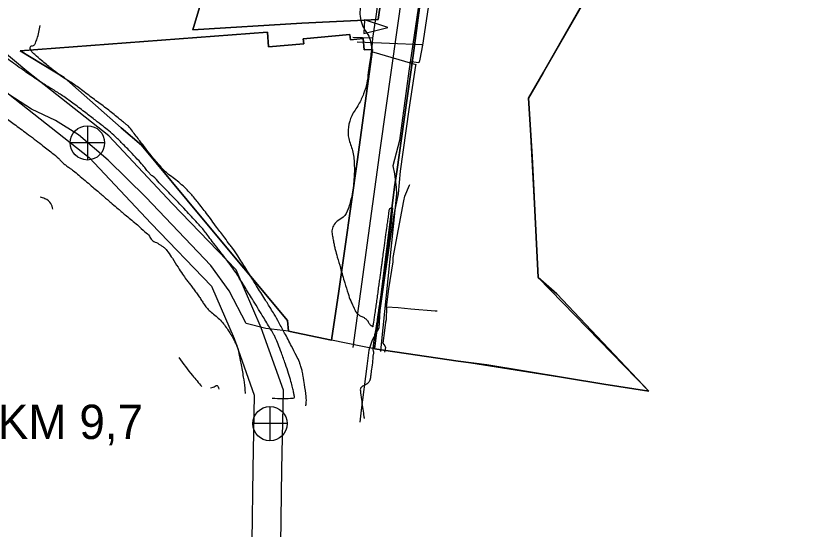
# Model space of a CAD drawing. Extents: x -478232 to -472707, y -1118753 to -1113967.
# Drawn here: x -476056.2 to -475825.3, y -1117737.7 to -1117588.2 of the extents above; entities that cross this region are included whole.
import ezdxf

# ---------------------------------------------------------------- set-up
doc = ezdxf.new("R2010")
doc.units = 0
for name, color, linetype in [('cesty', 7, 'Continuous'), ('nesmenovane pozemky', 7, 'Continuous'), ('ObPÚ', 7, 'Continuous'), ('plyn_stl', 7, 'Continuous'), ('silnice', 7, 'Continuous'), ('staničení toku', 7, 'Continuous'), ('telekomunikační kabel_O2', 7, 'Continuous'), ('VAK_vodovod', 7, 'Continuous'), ('VAK_vodovod_přípojky', 7, 'Continuous'), ('vodní plochy', 7, 'Continuous'), ('Vrstevnice_hlavni', 7, 'Continuous'), ('Vrstevnice_vedlejsi', 7, 'Continuous')]:
    doc.layers.add(name, color=color, linetype=linetype)

msp = doc.modelspace()

# ---------------------------------------------------------------- linework, layer by layer
at = {"layer": 'cesty'}
msp.add_line((-475954.611, -1117589.335), (-475954.743, -1117593.333), dxfattribs=at)
msp.add_lwpolyline([(-475954.743, -1117593.333), (-475947.734, -1117591.563), (-475954.611, -1117589.335)], dxfattribs=at)
at = {"layer": 'nesmenovane pozemky'}
for p, q in [((-475982.83, -1117592.88), (-476054.95, -1117598.38)), ((-475958.8, -1117593.62), (-475972.41, -1117594.83)), ((-475958.67, -1117595.15), (-475958.8, -1117593.62)), ((-475972.41, -1117594.83), (-475972.26, -1117596.35)), ((-475956.76, -1117594.96), (-475958.67, -1117595.15)), ((-475954.99, -1117594.75), (-475956.76, -1117594.96)), ((-476054.95, -1117598.38), (-476042.1, -1117606.13)), ((-476042.1, -1117606.13), (-476028.77, -1117617.9)), ((-476028.77, -1117617.9), (-476025.49, -1117620.79)), ((-476025.49, -1117620.79), (-476019.54, -1117625.79)), ((-476019.54, -1117625.79), (-476001.99, -1117647.03)), ((-475962.01, -1117668.38), (-475956.69, -1117630.64)), ((-476001.99, -1117647.03), (-475977.06, -1117676.86))]:
    msp.add_line(p, q, dxfattribs=at)
for points in [[(-475951.7, -1117685.1), (-475927.26, -1117688.72), (-475918.95, -1117689.8), (-475884.78, -1117695.44), (-475871.68, -1117697.52), (-475898.5, -1117669.12), (-475903.93, -1117664.35), (-475905.71, -1117629.13), (-475906.78, -1117612.16), (-475902.49, -1117604.75), (-475882.63, -1117570.25), (-475876.2, -1117558.77), (-475871.25, -1117549.71), (-475870.12, -1117548.49), (-475868.56, -1117541.56), (-475866.64, -1117537.01), (-475865.5, -1117532.56), (-475858.35, -1117525.46), (-475844.8, -1117506.28), (-475833.86, -1117486.94), (-475831.88, -1117483.59), (-475829.4, -1117473.48), (-475914.94, -1117458.35), (-475916.88, -1117458.16)], [(-475937.08, -1117500.29), (-475943.5, -1117540.53), (-475950.59, -1117589.22), (-475972.84, -1117590.29), (-476004.64, -1117592.26), (-475999.55, -1117575.26), (-475994.23, -1117573.44), (-475992.2, -1117563.25), (-475986.19, -1117534.11), (-475984.93, -1117525.82), (-475982.04, -1117518.19), (-475972.81, -1117513.2), (-475947.17, -1117503.84), (-475937.08, -1117500.29)], [(-475947.17, -1117503.84), (-475972.81, -1117513.2), (-475982.04, -1117518.19), (-475984.93, -1117525.82), (-475986.19, -1117534.11), (-475992.2, -1117563.25), (-475994.23, -1117573.44), (-475999.55, -1117575.26), (-476004.64, -1117592.26), (-475972.84, -1117590.29), (-475950.59, -1117589.22), (-475943.5, -1117540.53), (-475937.08, -1117500.29), (-475947.17, -1117503.84)], [(-475936.13, -1117566.09), (-475938.19, -1117582.83), (-475940.34, -1117599.73)], [(-475882.63, -1117570.25), (-475902.49, -1117604.75), (-475906.78, -1117612.16), (-475905.71, -1117629.13), (-475903.93, -1117664.35), (-475898.5, -1117669.12), (-475871.68, -1117697.52), (-475884.78, -1117695.44), (-475918.95, -1117689.8), (-475927.26, -1117688.72), (-475951.7, -1117685.1), (-475945.87, -1117637.95), (-475945.03, -1117632.93), (-475943.79, -1117623.91), (-475940.34, -1117599.73), (-475938.19, -1117582.83)], [(-476054.95, -1117598.38), (-475982.83, -1117592.88), (-475982.54, -1117597.23), (-475972.26, -1117596.35), (-475972.41, -1117594.83), (-475958.8, -1117593.62), (-475958.67, -1117595.15), (-475956.76, -1117594.96), (-475954.99, -1117594.75), (-475954.64, -1117598.05), (-475952.28, -1117597.96), (-475956.69, -1117630.64), (-475962.01, -1117668.38), (-475964.23, -1117682.64), (-475976.69, -1117679.99), (-475977.06, -1117676.86), (-476001.99, -1117647.03), (-476019.54, -1117625.79), (-476025.49, -1117620.79), (-476028.77, -1117617.9), (-476042.1, -1117606.13), (-476054.95, -1117598.38)], [(-475972.26, -1117596.35), (-475982.54, -1117597.23), (-475982.83, -1117592.88)], [(-475956.69, -1117630.64), (-475952.28, -1117597.96), (-475954.64, -1117598.05), (-475954.99, -1117594.75)], [(-475940.34, -1117599.73), (-475943.79, -1117623.91), (-475945.03, -1117632.93), (-475945.87, -1117637.95), (-475951.7, -1117685.1)], [(-475977.06, -1117676.86), (-475976.69, -1117679.99), (-475964.23, -1117682.64), (-475962.01, -1117668.38)]]:
    msp.add_lwpolyline(points, dxfattribs=at)
at = {"layer": 'ObPÚ'}
for points in [[(-475797.1, -1117434.24), (-475812.51, -1117451.24), (-475815.72, -1117464.29), (-475829.4, -1117473.48), (-475831.88, -1117483.59), (-475844.8, -1117506.28), (-475858.35, -1117525.46), (-475865.5, -1117532.56), (-475866.64, -1117537.01), (-475868.56, -1117541.56), (-475870.12, -1117548.49), (-475871.25, -1117549.71), (-475906.78, -1117612.16), (-475903.93, -1117664.35), (-475871.68, -1117697.52), (-475884.78, -1117695.44), (-475927.26, -1117688.72), (-475927.26, -1117688.72), (-475951.7, -1117685.1), (-475955.15, -1117684.42), (-475964.23, -1117682.64), (-475976.69, -1117679.99)], [(-475976.69, -1117679.99), (-475983.33, -1117679.27), (-475989.02, -1117677.74), (-475994.01, -1117668.3), (-475999.39, -1117660.91), (-476018.27, -1117641.02), (-476029.29, -1117630.21), (-476037.95, -1117622.81), (-476044.67, -1117618.64), (-476051.59, -1117615.33), (-476061.64, -1117608.91), (-476079.88, -1117594.07), (-476091, -1117580.9), (-476108.8, -1117553.82), (-476114, -1117528.42), (-476124.29, -1117530.11), (-476161.03, -1117531.19), (-476195.86, -1117533.14), (-476234.26, -1117534.63), (-476239.28, -1117534.9), (-476242.12, -1117534.97), (-476268.08, -1117536.08), (-476315.84, -1117537.76), (-476383.34, -1117541.03)]]:
    msp.add_lwpolyline(points, dxfattribs=at)
at = {"layer": 'plyn_stl'}
msp.add_line((-475952.244, -1117594.708), (-475958, -1117594.481), dxfattribs=at)
msp.add_lwpolyline([(-475950.891, -1117585.581), (-475951.277, -1117588.32), (-475951.277, -1117588.32), (-475952.244, -1117594.708), (-475952.569, -1117598.534), (-475951.885, -1117598.735), (-475939.635, -1117602.325), (-475939.681, -1117602.62), (-475941.682, -1117615.413), (-475944.166, -1117633.413), (-475944.166, -1117633.413), (-475944.769, -1117640.016), (-475945.933, -1117645.497), (-475946.953, -1117652.292), (-475950.061, -1117674.019), (-475950.384, -1117679.114), (-475952.306, -1117682.652), (-475953.329, -1117685.537), (-475953.931, -1117690.234), (-475955.586, -1117703.027), (-475955.894, -1117706.481)], dxfattribs=at)
at = {"layer": 'silnice'}
msp.add_lwpolyline([(-475957.898, -1117684.778), (-475949.882, -1117626.621), (-475938.626, -1117546.976), (-475927.029, -1117479.269), (-475917.649, -1117429.299), (-475903.982, -1117378.322)], dxfattribs=at)
at = {"layer": 'staničení toku'}
for p, q in [((-476035.323, -1117620.153), (-476035.323, -1117630.153)), ((-476030.323, -1117625.153), (-476040.323, -1117625.153)), ((-475982.122, -1117701.934), (-475982.122, -1117711.934)), ((-475977.122, -1117706.934), (-475987.122, -1117706.934))]:
    msp.add_line(p, q, dxfattribs=at)
for centre in [(-476035.323, -1117625.153), (-475982.122, -1117706.934)]:
    msp.add_circle(centre, 5, dxfattribs=at)
at = {"layer": 'telekomunikační kabel_O2'}
for points in [[(-475931.82, -1117535.04), (-475932.74, -1117541.33), (-475934.27, -1117556.02), (-475935.89, -1117566.02), (-475937.71, -1117577.81), (-475938.91, -1117585.91), (-475941.61, -1117604.26), (-475944.33, -1117624.51)], [(-475944.33, -1117624.51), (-475946.3, -1117631.82), (-475945.82, -1117634.15), (-475945.36, -1117638.18), (-475945.21, -1117640.05), (-475949.75, -1117683.81), (-475949.948, -1117685.946)], [(-475948.15, -1117672.99), (-475947.43, -1117667.7), (-475946.22, -1117659.8), (-475946.19, -1117658.58), (-475944.69, -1117650.28), (-475943.14, -1117642.06), (-475942.8, -1117640.69), (-475941.43, -1117637.45), (-475941.34, -1117637.26)], [(-475948.15, -1117672.99), (-475948.29, -1117676.74), (-475948.48, -1117677.36), (-475948.75, -1117679.85), (-475949.19, -1117683.52), (-475948.61, -1117684.28), (-475948.44, -1117684.72), (-475948.762, -1117686.113)], [(-475933.35, -1117674.2), (-475933.99, -1117674.13), (-475941.04, -1117673.59), (-475944.77, -1117673.16), (-475948.15, -1117672.99)]]:
    msp.add_lwpolyline(points, dxfattribs=at)
at = {"layer": 'VAK_vodovod'}
msp.add_lwpolyline([(-475961.022, -1117076.006), (-475947.88, -1117107.78), (-475947.26, -1117108.989), (-475886.863, -1117255.251), (-475879.338, -1117287.714), (-475878.218, -1117296.341), (-475877.862, -1117316.562), (-475878.829, -1117320.819), (-475879.236, -1117324.31), (-475879.403, -1117324.54), (-475921.268, -1117487.378), (-475934.347, -1117574.649), (-475937.667, -1117596.666), (-475938.465, -1117600.746), (-475938.582, -1117601.233), (-475938.757, -1117601.897), (-475940.979, -1117601.583)], dxfattribs=at)
at = {"layer": 'VAK_vodovod_přípojky'}
msp.add_lwpolyline([(-475937.667, -1117596.666), (-475937.9, -1117596.654), (-475956.701, -1117595.856)], dxfattribs=at)
at = {"layer": 'vodní plochy'}
for points in [[(-476156.309, -1117361.66), (-476163.99, -1117375.673), (-476163.99, -1117389.902), (-476152.92, -1117410.923), (-476142.297, -1117430.597), (-476130.77, -1117459.77), (-476124.441, -1117494.592), (-476117.774, -1117517.884), (-476114.889, -1117528.175), (-476108.171, -1117553.375), (-476083.318, -1117589.997), (-476058.349, -1117610.854), (-476034.844, -1117629.396), (-476016.763, -1117648.618), (-475999.131, -1117666.937), (-475992.574, -1117682.093), (-475986.696, -1117698.606), (-475987.148, -1117720.093), (-475987.374, -1117741.294), (-475990.765, -1117763.06), (-476002.517, -1117812.638), (-476018.337, -1117866.341), (-476031.898, -1117910.436), (-476051.109, -1117946.052)], [(-476043.664, -1117950.068), (-476024.057, -1117913.719), (-476010.237, -1117868.779), (-475994.339, -1117814.81), (-475982.458, -1117764.689), (-475978.922, -1117741.994), (-475978.69, -1117720.226), (-475978.206, -1117697.232), (-475984.699, -1117678.992), (-475991.975, -1117662.174), (-476010.635, -1117642.787), (-476029.112, -1117623.144), (-476053.017, -1117604.286), (-476076.984, -1117584.266), (-476100.367, -1117549.811), (-476106.73, -1117525.944), (-476109.636, -1117515.578), (-476116.194, -1117492.667), (-476122.596, -1117457.437), (-476134.615, -1117427.02), (-476145.456, -1117406.943), (-476155.531, -1117387.811), (-476155.531, -1117377.84), (-476148.691, -1117365.336)]]:
    msp.add_lwpolyline(points, dxfattribs=at)
at = {"layer": 'Vrstevnice_hlavni'}
for points in [[(-475971.717, -1117701.762), (-475971.607, -1117701.252), (-475971.588, -1117698.984), (-475972.084, -1117695.558), (-475972.453, -1117693.121), (-475972.695, -1117691.672), (-475972.81, -1117691.21), (-475972.989, -1117690.616), (-475973.23, -1117689.89), (-475973.535, -1117689.032), (-475974.407, -1117687.189), (-475975.847, -1117684.359), (-475977.854, -1117680.544), (-475979.53, -1117677.451), (-475980.877, -1117675.08), (-475981.894, -1117673.431), (-475983.613, -1117670.663), (-475986.035, -1117666.775), (-475989.159, -1117661.767), (-475991.493, -1117658.108), (-475993.035, -1117655.798), (-475993.787, -1117654.837), (-475995.305, -1117652.833), (-475997.589, -1117649.787), (-476000.639, -1117645.698), (-476003.172, -1117642.447), (-476005.187, -1117640.031), (-476006.686, -1117638.453), (-476008.271, -1117636.98), (-476009.945, -1117635.611), (-476011.706, -1117634.347), (-476013.975, -1117632.09), (-476016.751, -1117628.84), (-476020.034, -1117624.596), (-476022.231, -1117621.758), (-476023.343, -1117620.326), (-476023.368, -1117620.3), (-476023.492, -1117620.197), (-476023.714, -1117620.018), (-476024.035, -1117619.763), (-476024.775, -1117619.164), (-476025.934, -1117618.221), (-476027.511, -1117616.935), (-476029.117, -1117615.669), (-476030.752, -1117614.422), (-476032.416, -1117613.195), (-476034.102, -1117611.941), (-476035.809, -1117610.661), (-476037.537, -1117609.353), (-476039.113, -1117608.231), (-476040.537, -1117607.296), (-476041.807, -1117606.547), (-476043.59, -1117605.281), (-476045.886, -1117603.499), (-476048.694, -1117601.201), (-476050.647, -1117599.461), (-476051.746, -1117598.281), (-476051.991, -1117597.66), (-476051.957, -1117597.21), (-476051.643, -1117596.932), (-476051.051, -1117596.824), (-476050.503, -1117596.11), (-476050.001, -1117594.788), (-476049.087, -1117590.932)], [(-476045.367, -1117644.51), (-476045.958, -1117642.834), (-476047.71, -1117641.434), (-476049.108, -1117640.973)], [(-476008.671, -1117687.695), (-476004.74, -1117692.892), (-476001.978, -1117696.103)], [(-475999.442, -1117696.51), (-475998.676, -1117696.339), (-475997.525, -1117695.856), (-475997.026, -1117696.899)]]:
    msp.add_spline(points, degree=3, dxfattribs=at)
at = {"layer": 'Vrstevnice_vedlejsi'}
for points in [[(-475925.807, -1117448.34), (-475926.271, -1117450.621), (-475926.743, -1117453.028), (-475927.223, -1117455.562), (-475927.71, -1117458.222), (-475928.119, -1117460.397), (-475928.448, -1117462.085), (-475928.698, -1117463.287), (-475929.008, -1117464.755), (-475929.377, -1117466.489), (-475929.805, -1117468.489), (-475930.153, -1117470.183), (-475930.42, -1117471.572), (-475930.607, -1117472.656), (-475930.864, -1117474.203), (-475931.192, -1117476.212), (-475931.591, -1117478.685), (-475931.911, -1117480.673), (-475932.154, -1117482.178), (-475932.319, -1117483.199), (-475932.507, -1117484.336), (-475932.716, -1117485.589), (-475932.947, -1117486.958), (-475933.165, -1117488.181), (-475933.369, -1117489.257), (-475933.56, -1117490.186), (-475933.776, -1117491.179), (-475934.018, -1117492.236), (-475934.284, -1117493.357), (-475934.519, -1117494.236), (-475934.723, -1117494.873), (-475934.895, -1117495.268), (-475935.041, -1117495.607), (-475935.161, -1117495.889), (-475935.254, -1117496.115), (-475935.322, -1117496.274), (-475935.366, -1117496.367), (-475935.386, -1117496.394), (-475935.348, -1117496.507), (-475935.253, -1117496.706), (-475935.101, -1117496.991), (-475935.105, -1117497.404), (-475935.264, -1117497.944), (-475935.579, -1117498.612), (-475935.962, -1117499.972), (-475936.413, -1117502.024), (-475936.932, -1117504.768), (-475937.635, -1117508.885), (-475938.521, -1117514.375), (-475939.592, -1117521.239), (-475940.344, -1117525.997), (-475940.776, -1117528.651), (-475940.89, -1117529.2), (-475940.962, -1117529.609), (-475940.994, -1117529.877), (-475940.984, -1117530.005), (-475940.975, -1117530.143), (-475940.967, -1117530.29), (-475940.96, -1117530.446), (-475940.993, -1117530.576), (-475941.066, -1117530.679), (-475941.18, -1117530.754), (-475941.378, -1117530.99), (-475941.658, -1117531.386), (-475942.021, -1117531.943), (-475942.311, -1117532.508), (-475942.528, -1117533.081), (-475942.672, -1117533.663), (-475942.827, -1117534.113), (-475942.993, -1117534.43), (-475943.171, -1117534.615), (-475943.259, -1117535.054), (-475943.258, -1117535.746), (-475943.166, -1117536.692), (-475943.05, -1117537.531), (-475942.909, -1117538.261), (-475942.742, -1117538.884), (-475942.673, -1117539.509), (-475942.701, -1117540.138), (-475942.826, -1117540.769), (-475943.252, -1117541.788), (-475943.979, -1117543.194), (-475945.007, -1117544.986), (-475946.021, -1117548.378), (-475947.023, -1117553.369), (-475948.011, -1117559.959), (-475949.315, -1117565.973), (-475950.935, -1117571.413), (-475952.871, -1117576.278), (-475954.339, -1117580.395), (-475955.339, -1117583.764), (-475955.87, -1117586.385), (-475955.761, -1117588.893), (-475955.011, -1117591.286), (-475953.62, -1117593.565), (-475952.783, -1117595.731), (-475952.5, -1117597.782)], [(-475981.46, -1117699.481), (-475978.555, -1117699.624), (-475976.129, -1117699.562), (-475974.954, -1117699.271), (-475975.03, -1117698.751), (-475975.228, -1117697.811), (-475975.55, -1117696.45), (-475975.994, -1117694.67), (-475976.683, -1117692.38), (-475977.615, -1117689.58), (-475978.79, -1117686.27), (-475979.742, -1117683.744), (-475980.471, -1117682), (-475980.976, -1117681.039), (-475982.274, -1117678.84), (-475984.365, -1117675.402), (-475987.248, -1117670.725), (-475989.482, -1117667.108), (-475991.066, -1117664.551), (-475992, -1117663.054), (-475993.334, -1117661.147), (-475995.067, -1117658.83), (-475997.2, -1117656.104), (-475998.937, -1117653.864), (-476000.278, -1117652.111), (-476001.223, -1117650.844), (-476003.359, -1117648.412), (-476006.686, -1117644.817), (-476011.205, -1117640.057), (-476014.372, -1117636.772), (-476016.189, -1117634.963), (-476016.654, -1117634.629), (-476017.253, -1117634.033), (-476017.986, -1117633.174), (-476018.854, -1117632.053), (-476020.293, -1117630.419), (-476022.304, -1117628.273), (-476024.886, -1117625.614), (-476027.159, -1117623.402), (-476029.122, -1117621.638), (-476030.775, -1117620.322), (-476033.001, -1117618.591), (-476035.8, -1117616.445), (-476039.172, -1117613.884), (-476042.252, -1117611.681), (-476045.041, -1117609.835), (-476047.539, -1117608.347), (-476050.577, -1117606.371), (-476054.156, -1117603.908), (-476058.275, -1117600.957), (-476062.207, -1117598.083), (-476065.949, -1117595.284), (-476069.503, -1117592.56), (-476072.061, -1117590.57), (-476073.624, -1117589.313), (-476074.192, -1117588.788), (-476074.683, -1117588.4), (-476075.099, -1117588.149), (-476075.44, -1117588.034), (-476076.24, -1117587.297), (-476077.502, -1117585.938), (-476079.224, -1117583.956), (-476080.447, -1117582.527), (-476081.171, -1117581.65), (-476081.395, -1117581.326), (-476081.696, -1117580.862), (-476082.073, -1117580.259), (-476082.526, -1117579.516), (-476083.525, -1117577.807), (-476085.071, -1117575.131), (-476087.164, -1117571.488), (-476088.854, -1117568.526), (-476090.141, -1117566.244), (-476091.025, -1117564.644), (-476092.063, -1117562.712), (-476093.256, -1117560.449), (-476094.602, -1117557.855), (-476095.618, -1117555.794), (-476096.304, -1117554.266), (-476096.659, -1117553.272), (-476097.351, -1117551.32), (-476098.38, -1117548.411), (-476099.746, -1117544.544), (-476100.765, -1117541.586), (-476101.438, -1117539.537), (-476101.763, -1117538.395), (-476102.235, -1117536.609), (-476102.852, -1117534.179), (-476103.615, -1117531.104), (-476104.476, -1117527.462), (-476105.437, -1117523.255)], [(-476106.817, -1117565.137), (-476105.765, -1117567.124), (-476104.847, -1117568.952), (-476104.064, -1117570.621), (-476103.415, -1117572.131), (-476102.764, -1117573.351), (-476102.11, -1117574.281), (-476101.453, -1117574.921), (-476100.89, -1117575.71), (-476100.42, -1117576.65), (-476100.044, -1117577.739), (-476099.46, -1117578.945), (-476098.67, -1117580.267), (-476097.672, -1117581.706), (-476096.764, -1117583.004), (-476095.947, -1117584.161), (-476095.22, -1117585.179), (-476094.396, -1117586.266), (-476093.475, -1117587.421), (-476092.456, -1117588.646), (-476091.223, -1117590.178), (-476089.774, -1117592.02), (-476088.11, -1117594.169), (-476086.729, -1117595.938), (-476085.632, -1117597.326), (-476084.818, -1117598.334), (-476083.928, -1117599.313), (-476082.959, -1117600.263), (-476081.914, -1117601.183), (-476080.423, -1117602.407), (-476078.488, -1117603.934), (-476076.108, -1117605.764), (-476073.547, -1117607.692), (-476070.805, -1117609.717), (-476067.883, -1117611.841), (-476065.083, -1117613.835), (-476062.404, -1117615.699), (-476059.847, -1117617.433), (-476056.711, -1117619.675), (-476052.997, -1117622.425), (-476048.704, -1117625.682), (-476045.603, -1117628.112), (-476043.694, -1117629.717), (-476042.976, -1117630.495), (-476042.176, -1117631.234), (-476041.295, -1117631.933), (-476040.332, -1117632.593), (-476039.042, -1117633.586), (-476037.424, -1117634.912), (-476035.478, -1117636.572), (-476033.782, -1117638.02), (-476032.334, -1117639.257), (-476031.136, -1117640.282), (-476030.03, -1117641.234), (-476029.016, -1117642.113), (-476028.094, -1117642.919), (-476026.414, -1117644.345), (-476023.977, -1117646.392), (-476020.782, -1117649.059), (-476018.552, -1117651.039), (-476017.285, -1117652.33), (-476016.983, -1117652.934), (-476016.538, -1117653.449), (-476015.951, -1117653.878), (-476015.222, -1117654.218), (-476014.48, -1117654.627), (-476013.723, -1117655.103), (-476012.952, -1117655.648), (-476011.894, -1117656.876), (-476010.549, -1117658.788), (-476008.916, -1117661.383), (-476007.581, -1117663.43), (-476006.542, -1117664.929), (-476005.801, -1117665.879), (-476005.026, -1117666.896), (-476004.217, -1117667.979), (-476003.374, -1117669.128), (-476002.599, -1117670.236), (-476001.892, -1117671.303), (-476001.253, -1117672.328), (-476000.365, -1117673.387), (-475999.228, -1117674.478), (-475997.842, -1117675.601), (-475996.573, -1117676.834), (-475995.422, -1117678.178), (-475994.388, -1117679.632), (-475993.585, -1117680.835), (-475993.014, -1117681.788), (-475992.673, -1117682.49), (-475992.335, -1117683.187), (-475992.001, -1117683.877), (-475991.669, -1117684.563), (-475991.211, -1117686.377), (-475990.625, -1117689.321), (-475989.912, -1117693.394), (-475989.476, -1117696.56), (-475989.366, -1117698.131)], [(-475952.5, -1117597.782), (-475952.77, -1117599.72), (-475953.091, -1117602.026), (-475953.464, -1117604.702), (-475953.888, -1117607.746), (-475954.833, -1117610.851), (-475956.298, -1117614.016), (-475958.285, -1117617.241), (-475959.241, -1117620.546), (-475959.167, -1117623.929), (-475958.062, -1117627.391), (-475957.55, -1117631.337), (-475957.632, -1117635.767), (-475958.306, -1117640.68), (-475959.346, -1117644.356), (-475960.749, -1117646.793), (-475962.518, -1117647.993), (-475963.629, -1117649.309), (-475964.082, -1117650.743), (-475963.877, -1117652.294), (-475963.645, -1117653.721), (-475963.384, -1117655.024), (-475963.095, -1117656.203), (-475962.492, -1117658.405), (-475961.573, -1117661.63), (-475960.339, -1117665.877), (-475959.343, -1117669.07), (-475958.586, -1117671.21), (-475958.067, -1117672.297), (-475957.63, -1117673.208), (-475957.276, -1117673.943), (-475957.004, -1117674.503), (-475956.518, -1117675.025), (-475955.817, -1117675.509), (-475954.903, -1117675.956), (-475954.175, -1117676.457), (-475953.635, -1117677.013), (-475953.282, -1117677.625), (-475953.011, -1117678.047), (-475952.822, -1117678.278), (-475952.716, -1117678.319), (-475952.602, -1117678.375), (-475952.481, -1117678.448), (-475952.352, -1117678.536), (-475952.255, -1117678.608), (-475952.187, -1117678.663), (-475952.151, -1117678.703), (-475952.112, -1117678.658), (-475952.07, -1117678.528), (-475952.027, -1117678.315), (-475951.976, -1117678.042), (-475951.92, -1117677.709), (-475951.857, -1117677.317), (-475951.729, -1117676.466), (-475951.537, -1117675.156), (-475951.279, -1117673.387), (-475951.021, -1117671.579), (-475950.762, -1117669.733), (-475950.503, -1117667.848), (-475950.264, -1117666.119), (-475950.045, -1117664.545), (-475949.847, -1117663.128), (-475949.666, -1117661.812), (-475949.504, -1117660.597), (-475949.36, -1117659.484), (-475949.115, -1117657.659), (-475948.768, -1117655.123), (-475948.321, -1117651.875), (-475947.98, -1117649.406), (-475947.748, -1117647.714), (-475947.623, -1117646.8), (-475947.526, -1117646.071), (-475947.458, -1117645.526), (-475947.417, -1117645.165), (-475947.363, -1117644.859), (-475947.296, -1117644.61), (-475947.214, -1117644.416), (-475947.148, -1117644.279), (-475947.098, -1117644.198), (-475947.063, -1117644.174), (-475946.98, -1117644.151), (-475946.847, -1117644.128), (-475946.666, -1117644.106), (-475946.54, -1117644.093), (-475946.469, -1117644.091), (-475946.454, -1117644.099), (-475946.445, -1117644.165), (-475946.442, -1117644.29), (-475946.446, -1117644.473), (-475946.485, -1117644.987), (-475946.559, -1117645.833), (-475946.669, -1117647.01), (-475946.781, -1117648.065), (-475946.896, -1117648.998), (-475947.013, -1117649.81), (-475947.196, -1117651.112), (-475947.445, -1117652.904)], [(-475947.445, -1117652.904), (-475947.76, -1117655.187), (-475948, -1117656.984), (-475948.167, -1117658.294), (-475948.261, -1117659.118), (-475948.359, -1117659.927), (-475948.464, -1117660.721), (-475948.573, -1117661.5), (-475948.817, -1117663.109), (-475949.196, -1117665.548), (-475949.708, -1117668.818), (-475950.095, -1117671.313), (-475950.356, -1117673.034), (-475950.492, -1117673.979), (-475950.661, -1117675.15), (-475950.863, -1117676.547), (-475951.099, -1117678.169), (-475951.302, -1117679.471), (-475951.471, -1117680.453), (-475951.607, -1117681.115), (-475951.736, -1117681.862), (-475951.858, -1117682.692), (-475951.973, -1117683.605), (-475952.055, -1117684.326), (-475952.104, -1117684.853), (-475952.12, -1117685.187), (-475952.106, -1117685.469), (-475952.061, -1117685.701), (-475951.987, -1117685.881), (-475952.039, -1117686.837), (-475952.217, -1117688.57), (-475952.52, -1117691.078), (-475952.747, -1117692.851), (-475952.897, -1117693.887), (-475952.97, -1117694.188), (-475953.11, -1117694.497), (-475953.315, -1117694.816), (-475953.587, -1117695.144), (-475953.983, -1117695.455), (-475954.502, -1117695.75), (-475955.145, -1117696.027), (-475955.572, -1117696.384), (-475955.783, -1117696.819), (-475955.778, -1117697.332), (-475955.459, -1117699.866), (-475954.827, -1117704.42), (-475954.679, -1117705.478)]]:
    msp.add_spline(points, degree=3, dxfattribs=at)

# ---------------------------------------------------------------- texts
at = {"layer": 'staničení toku'}
msp.add_text('KM 9,7', height=10, rotation=359.98161, dxfattribs=at).set_placement((-476061.465, -1117711.404))

doc.saveas('drawing.dxf')
